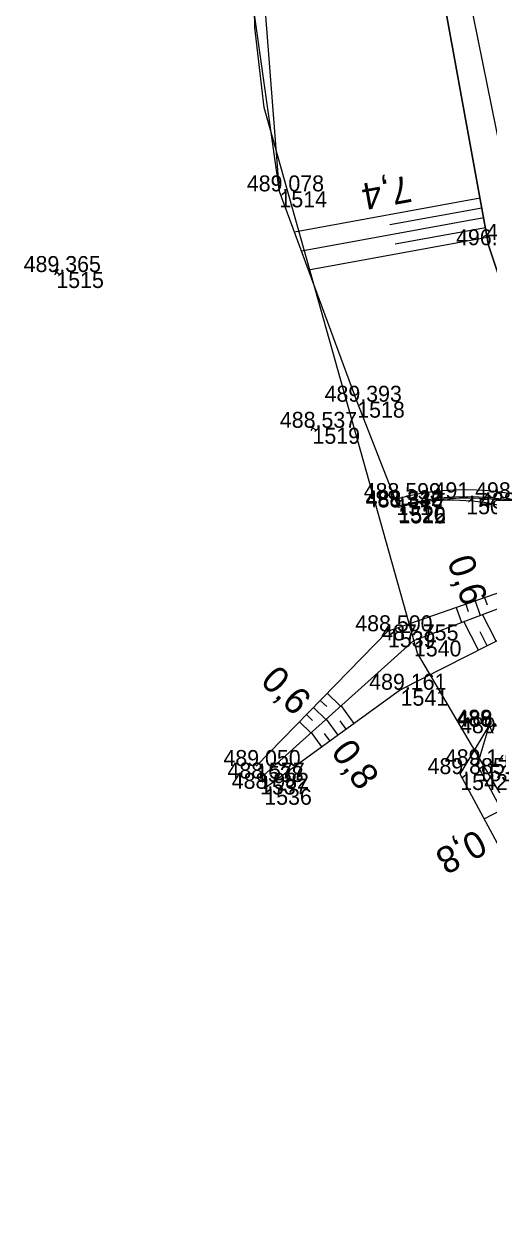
# Model space of a CAD drawing. Extents: x -1234191 to 23050, y -1290331 to -741191.
# Drawn here: x -865317 to -865282.1, y -1106989.1 to -1106898.4 of the extents above; entities that cross this region are included whole.
import ezdxf

# ---------------------------------------------------------------- set-up
doc = ezdxf.new("R2010")
doc.units = 0
for name, color, linetype in [('Vrstva 18', 7, 'Continuous'), ('Vrstva 4', 7, 'Continuous'), ('Vrstva 48', 7, 'Continuous'), ('Vrstva 49', 7, 'Continuous'), ('Vrstva 53', 7, 'Continuous'), ('Vrstva 60', 7, 'Continuous'), ('Vrstva 61', 7, 'Continuous')]:
    doc.layers.add(name, color=color, linetype=linetype)

msp = doc.modelspace()

# ---------------------------------------------------------------- linework, layer by layer
at = {"layer": 'Vrstva 18'}
msp.add_lwpolyline([(-865289.02, -1106934.075), (-865288.886, -1106934.608), (-865288.865, -1106934.705), (-865288.865, -1106934.705), (-865289.02, -1106934.075)], dxfattribs=at)
for centre, major_axis, ratio, start_param, end_param in [((-865283.448, -1106960.633), (-1.435, 27.22), 0.851193, 5.864678, 6.463727), ((-865283.531, -1106961.28), (-0.604, 27.357), 0.850466, 5.890013, 6.489406), ((-865284.932, -1106951.919), (-17.861, 0.324), 0.993641, 4.122228, 4.953601), ((-865283.51, -1106961.381), (-0.608, 27.36), 0.850465, 5.889426, 6.489208), ((-865283.51, -1106961.381), (-0.608, 27.36), 0.850465, 5.889426, 6.489208)]:
    msp.add_ellipse(centre, major_axis=major_axis, ratio=ratio, start_param=start_param, end_param=end_param, dxfattribs=at)
at = {"layer": 'Vrstva 4'}
for points in [[(-865264.954, -1106688.91), (-865272.837, -1106712.229), (-865280.575, -1106736.798), (-865286.428, -1106761.048), (-865289.726, -1106786.08), (-865291.503, -1106811.498), (-865290.693, -1106838.142), (-865289.297, -1106864.373), (-865286.495, -1106890.765), (-865282.086, -1106914.996), (-865275.464, -1106934.873)], [(-865272.498, -1106944.548), (-865272.574, -1106944.571), (-865272.574, -1106944.571), (-865275.54, -1106934.896), (-865275.54, -1106934.896), (-865275.464, -1106934.873), (-865279.823, -1106914.594), (-865284.893, -1106889.515), (-865288.103, -1106864.147), (-865289.696, -1106838.091), (-865289.517, -1106811.54), (-865287.322, -1106786.54), (-865283.646, -1106761.541), (-865278.601, -1106737.213), (-865271.615, -1106713.21), (-865263.162, -1106689.661)]]:
    msp.add_lwpolyline(points, dxfattribs=at)
at = {"layer": 'Vrstva 48'}
for p, q in [((-865282.729, -1106911.463), (-865296.673, -1106914.001)), ((-865282.46, -1106912.939), (-865296.145, -1106915.429)), ((-865282.595, -1106912.201), (-865289.502, -1106913.458)), ((-865282.326, -1106913.677), (-865289.104, -1106914.91)), ((-865282.192, -1106914.415), (-865295.617, -1106916.858)), ((-865283.812, -1106941.978), (-865283.619, -1106942.533)), ((-865283.104, -1106941.731), (-865282.724, -1106942.822)), ((-865282.396, -1106941.484), (-865282.209, -1106942.02)), ((-865284.52, -1106942.225), (-865284.127, -1106943.353)), ((-865281.518, -1106944.756), (-865282.538, -1106942.752)), ((-865282.856, -1106945.436), (-865283.949, -1106943.285)), ((-865282.187, -1106945.096), (-865282.715, -1106944.057)), ((-865294.733, -1106949.206), (-865294.25, -1106949.678)), ((-865294.208, -1106948.67), (-865293.208, -1106949.648)), ((-865295.257, -1106949.742), (-865294.326, -1106950.653)), ((-865292.184, -1106950.941), (-865293.157, -1106949.603)), ((-865296.306, -1106950.814), (-865295.444, -1106951.657)), ((-865295.781, -1106950.278), (-865295.333, -1106950.717)), ((-865293.397, -1106951.823), (-865294.279, -1106950.61)), ((-865292.791, -1106951.382), (-865293.254, -1106950.744)), ((-865294.61, -1106952.705), (-865295.401, -1106951.618)), ((-865294.004, -1106952.264), (-865294.422, -1106951.689)), ((-865282.412, -1106958.118), (-865281.123, -1106957.428))]:
    msp.add_line(p, q, dxfattribs=at)
at = {"layer": 'Vrstva 49'}
for p, q in [((-865314.774, -1106916.87), (-865314.358, -1106917.148)), ((-865314.427, -1106916.801), (-865314.705, -1106917.217)), ((-865295.537, -1106928.596), (-865295.103, -1106928.844)), ((-865295.196, -1106928.503), (-865295.444, -1106928.937)), ((-865289.02, -1106934.075), (-865288.865, -1106934.705))]:
    msp.add_line(p, q, dxfattribs=at)
for points in [[(-865297.802, -1106910.945), (-865301.487, -1106884.828), (-865301.568, -1106862.296), (-865300.662, -1106837.393), (-865298.366, -1106810.159), (-865294.526, -1106785.601), (-865287.978, -1106760.271), (-865282.969, -1106736.073), (-865277.682, -1106710.809), (-865271.218, -1106686.119), (-865260.833, -1106663.971), (-865250.754, -1106645.729), (-865240.743, -1106625.956), (-865230.038, -1106606.795), (-865221.819, -1106591.382), (-865215.708, -1106580.006), (-865206.84, -1106567.395), (-865200.803, -1106554.973), (-865189.895, -1106532.431), (-865180.715, -1106509.043), (-865172.116, -1106485.465)], [(-865297.802, -1106910.945), (-865299.885, -1106884.19), (-865299.651, -1106862.604), (-865299.007, -1106836.911), (-865295.934, -1106809.856), (-865292.439, -1106784.8), (-865286.428, -1106761.048), (-865280.575, -1106736.798), (-865273.869, -1106712.177), (-865265.744, -1106688.568)], [(-865275.343, -1106935.266), (-865275.464, -1106934.873), (-865282.086, -1106914.996), (-865286.495, -1106890.765), (-865290.617, -1106864.175), (-865292.069, -1106837.428), (-865291.503, -1106811.498), (-865289.726, -1106786.08), (-865286.428, -1106761.048)], [(-865288.865, -1106934.705), (-865291.959, -1106926.757), (-865297.802, -1106910.945)], [(-865299.26, -1106955.083), (-865287.701, -1106944.704), (-865271.021, -1106938.397), (-865257.146, -1106935.564), (-865246.222, -1106932.911)], [(-865299.561, -1106954.142), (-865289.655, -1106944.015), (-865271.296, -1106937.614), (-865257.618, -1106934.632)], [(-865246.179, -1106934.125), (-865270.66, -1106939.236), (-865288.703, -1106948.409), (-865298.941, -1106955.855)], [(-865249.738, -1107007.477), (-865257.637, -1106994.452), (-865268.752, -1106978.915), (-865278.278, -1106965.835), (-865284.218, -1106954.747), (-865282.057, -1106951.112)], [(-865128.669, -1107224.012), (-865138.581, -1107199.148), (-865149.099, -1107176.459), (-865159.174, -1107156.369), (-865166.343, -1107143.763), (-865166.648, -1107142.995), (-865171.14, -1107136.463), (-865181.729, -1107117.736), (-865193.66, -1107097.685), (-865213.728, -1107062.352), (-865225.068, -1107044.055), (-865236.527, -1107025.406), (-865247.396, -1107006.442), (-865254.285, -1106995.006), (-865264.849, -1106980.548), (-865276.84, -1106965.358), (-865282.927, -1106954.089), (-865282.057, -1106951.112), (-865282.008, -1106951.196), (-865281.781, -1106951.679)]]:
    msp.add_lwpolyline(points, dxfattribs=at)
msp.add_ellipse((-865283.448, -1106960.633), major_axis=(-1.435, 27.22), ratio=0.851193, start_param=5.864678, end_param=6.463727, dxfattribs=at)
at = {"layer": 'Vrstva 53'}
msp.add_lwpolyline([(-865031.84, -1107728.7), (-865056.26, -1107614.01), (-865082.13, -1107527.34), (-865093.979, -1107443.046), (-865102.44, -1107349.87), (-865111.697, -1107288.183), (-865115.782, -1107279.624), (-865126.55, -1107239.39), (-865152.22, -1107173.12), (-865183.777, -1107119.15), (-865210.507, -1107089.362), (-865241.354, -1107035.567), (-865260.95, -1106990.6), (-865287.431, -1106945.67), (-865298.943, -1106904.637), (-865299.653, -1106898.631), (-865300.82, -1106833.27), (-865292.282, -1106759.439), (-865281.001, -1106690.918)], dxfattribs=at)
at = {"layer": 'Vrstva 60'}
for p, q in [((-865297.802, -1106910.945), (-865297.802, -1106910.945)), ((-865282.086, -1106914.996), (-865282.086, -1106914.996)), ((-865314.566, -1106917.009), (-865314.566, -1106917.009)), ((-865291.959, -1106926.757), (-865291.959, -1106926.757)), ((-865295.32, -1106928.72), (-865295.32, -1106928.72)), ((-865289.02, -1106934.075), (-865289.02, -1106934.075)), ((-865288.886, -1106934.608), (-865288.886, -1106934.608)), ((-865288.865, -1106934.705), (-865288.865, -1106934.705)), ((-865288.865, -1106934.705), (-865288.865, -1106934.705)), ((-865283.773, -1106934.016), (-865283.773, -1106934.016)), ((-865289.655, -1106944.015), (-865289.655, -1106944.015)), ((-865287.701, -1106944.704), (-865287.701, -1106944.704)), ((-865288.703, -1106948.409), (-865288.703, -1106948.409)), ((-865299.561, -1106954.142), (-865299.561, -1106954.142)), ((-865284.218, -1106954.747), (-865284.218, -1106954.747)), ((-865282.927, -1106954.089), (-865282.927, -1106954.089)), ((-865299.26, -1106955.083), (-865299.26, -1106955.083)), ((-865298.941, -1106955.855), (-865298.941, -1106955.855))]:
    msp.add_line(p, q, dxfattribs=at)

# ---------------------------------------------------------------- texts
at = {"layer": 'Vrstva 48'}
for s, rotation, p in [('7,4', 190.31255, (-865288.106, -1106909.736)), ('0,6', 289.22148, (-865285.225, -1106938.716)), ('0,6', 315.63205, (-865299.319, -1106947.852)), ('0,8', 306.02804, (-865294, -1106953.085)), ('0,8', 208.17859, (-865282.968, -1106958.85))]:
    msp.add_text(s, height=2, rotation=rotation, dxfattribs=at).set_placement(p)
at = {"layer": 'Vrstva 60'}
for s, p in [('1514', (-865297.802, -1106912.145)), ('1515', (-865314.566, -1106918.209)), ('1518', (-865291.959, -1106927.957)), ('1519', (-865295.32, -1106929.92)), ('1517', (-865289.02, -1106935.275)), ('1520', (-865288.886, -1106935.808)), ('1516', (-865288.865, -1106935.905)), ('1522', (-865288.865, -1106935.905)), ('1506', (-865283.773, -1106935.216)), ('1539', (-865289.655, -1106945.215)), ('1540', (-865287.701, -1106945.904)), ('1541', (-865288.703, -1106949.609)), ('1538', (-865299.561, -1106955.342)), ('1542', (-865284.218, -1106955.947)), ('1535', (-865282.927, -1106955.289)), ('1537', (-865299.26, -1106956.283)), ('1536', (-865298.941, -1106957.055))]:
    msp.add_text(s, height=1.2, dxfattribs=at).set_placement(p)
at = {"layer": 'Vrstva 61'}
for s, p in [('489.078', (-865300.256, -1106910.945)), ('496.512', (-865284.534, -1106914.996)), ('497.739', (-865282.277, -1106914.594)), ('489.365', (-865317.022, -1106917.009)), ('489.393', (-865294.411, -1106926.757)), ('488.537', (-865297.772, -1106928.72)), ('488.599', (-865291.474, -1106934.075)), ('491.498', (-865286.227, -1106934.016)), ('488.332', (-865291.334, -1106934.608)), ('488.510', (-865291.316, -1106934.705)), ('488.340', (-865291.316, -1106934.705)), ('488.330', (-865282.732, -1106934.782)), ('488.500', (-865292.106, -1106944.015)), ('487.755', (-865290.157, -1106944.704)), ('489.161', (-865291.06, -1106948.409)), ('489.059', (-865284.511, -1106951.112)), ('488.889', (-865284.511, -1106951.112)), ('488.868', (-865284.462, -1106951.196)), ('489.225', (-865284.237, -1106951.679)), ('489.050', (-865302.012, -1106954.142)), ('489.146', (-865285.379, -1106954.089)), ('488.577', (-865301.712, -1106955.083)), ('489.885', (-865286.674, -1106954.747)), ('488.982', (-865301.389, -1106955.855))]:
    msp.add_text(s, height=1.2, dxfattribs=at).set_placement(p)

doc.saveas('drawing.dxf')
